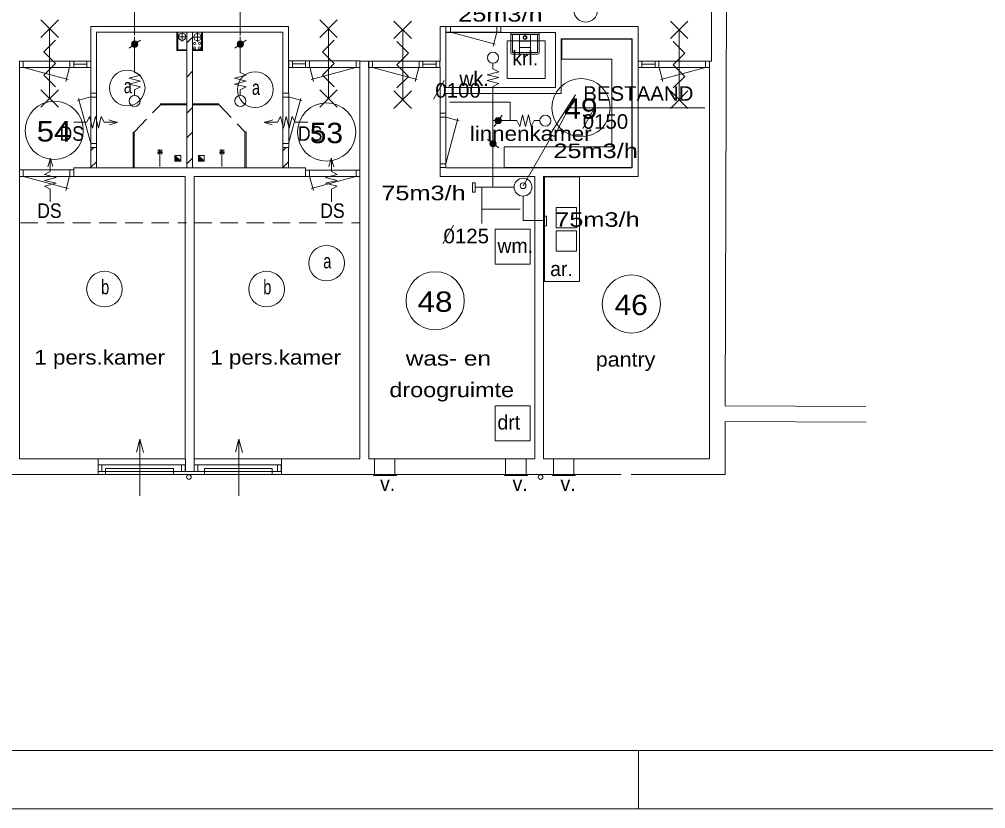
# Model space of a CAD drawing. Extents: x 295824 to 414724, y 24924 to 109024.
# Drawn here: x 320090 to 336685, y 24924 to 38482 of the extents above; entities that cross this region are included whole.
import ezdxf
from ezdxf.enums import TextEntityAlignment as Align

# ---------------------------------------------------------------- set-up
doc = ezdxf.new("R2010")
doc.units = 0
doc.header["$LTSCALE"] = 100
doc.linetypes.add('DOT_DASHED', pattern=[7.7, 5, -1.2, 0.3, -1.2])
doc.linetypes.add('MEDIUM_DASHED', pattern=[4.5, 3, -1.5])
for name, color, linetype, lineweight in [('1', 7, 'Continuous', 13), ('16', 7, 'Continuous', 13), ('24', 7, 'Continuous', 13), ('61', 7, 'Continuous', 13)]:
    doc.layers.add(name, color=color, linetype=linetype, lineweight=lineweight)

msp = doc.modelspace()

# ---------------------------------------------------------------- hatches: boundary and pattern name
at = {"layer": '24'}
for points in [[(322123.6, 38055.7, 1), (322015, 38055.7, 1)], [(323939.2, 38055.7, 1), (323830.6, 38055.7, 1)], [(328313.4, 36687.4, 1), (328313.4, 36796, 1)], [(328278.1, 36344.9, 1), (328169.5, 36344.9, 1)]]:
    msp.add_hatch(color=256, dxfattribs=at).paths.add_polyline_path(points)
at = {"layer": '61'}
for points in [[(322763.2, 36143.3), (322863.2, 36043.3), (322763.2, 36043.3)], [(323166.3, 36143.3), (323266.3, 36043.3), (323166.3, 36043.3)]]:
    msp.add_hatch(color=256, dxfattribs=at).paths.add_polyline_path(points)

# ---------------------------------------------------------------- linework, layer by layer
at = {"layer": '1'}
for p, q in [((322069.3, 38210.2), (322069.3, 39093.2)), ((323884.9, 38205.2), (323884.9, 39093.2)), ((328740.2, 35624.5), (329240.2, 36490.5)), ((330723.6, 24923.8), (330723.6, 25923.8)), ((304995.6, 24923.8), (414723.6, 24923.8))]:
    msp.add_line(p, q, dxfattribs=at)
msp.add_lwpolyline([(304995.6, 25923.8), (413723.6, 25923.8), (413723.6, 108023.8), (304995.6, 108023.8)], dxfattribs=at)
msp.add_lwpolyline([(329640.2, 37183.5), (329276.2, 36469.5), (329204.2, 36511.5)], close=True, dxfattribs=at)
msp.add_circle((328740.2, 35624.2), 50, dxfattribs=at)
at = {"layer": '16'}
for p, q in [((321396.7, 36814.4), (321346.7, 36614.4)), ((324674.2, 36814.4), (324724.2, 36614.4)), ((320520.3, 35716.2), (320720.3, 35666.2)), ((325550.6, 35716.2), (325350.6, 35666.2))]:
    msp.add_line(p, q, dxfattribs=at)
at = {"layer": '24'}
for p, q in [((322069.3, 37620.3), (322069.3, 38181)), ((323884.9, 37620.3), (323884.9, 38182.6)), ((321977.7, 37984.9), (322169.3, 38126.5)), ((323793.3, 37984.9), (323984.8, 38126.5)), ((327388, 37429.7), (327203.7, 37110.4)), ((328223.8, 37280.2), (328223.8, 35599.5)), ((329500.7, 36963.5), (331861.5, 36963.5)), ((329951, 36926.2), (329766.7, 36606.9)), ((321772.1, 36711), (321627.9, 36756)), ((321636.3, 36668.6), (321772.1, 36711)), ((324298.7, 36711), (324442.9, 36756)), ((324434.5, 36668.6), (324298.7, 36711)), ((328582.5, 36741.7), (328223.8, 36741.7)), ((328384.2, 36833.3), (328242.6, 36641.8)), ((328132.2, 36415.7), (328323.8, 36274)), ((320623.7, 36091.6), (320578.6, 35947.4)), ((320666.1, 35955.8), (320623.7, 36091.6)), ((325404.8, 35955.8), (325447.2, 36091.6)), ((325447.2, 36091.6), (325492.2, 35947.4)), ((328586.6, 35599.5), (327924, 35599.5)), ((328031, 35598.1), (328031, 34975.1)), ((328691.4, 35220.4), (328031, 35220.4)), ((327545.3, 34943.7), (327360.9, 34624.4)), ((322161, 31270.1), (322101.4, 31047.7)), ((323859.9, 31270.1), (323800.3, 31047.7))]:
    msp.add_line(p, q, dxfattribs=at)
for points in [[(328223.8, 37730.2), (328223.8, 37630.2), (328323.8, 37580.2), (328123.8, 37530.2), (328323.8, 37480.2), (328123.8, 37430.2), (328323.8, 37380.2), (328223.8, 37330.2), (328223.8, 37280.2)], [(322069.3, 37170.3), (322069.3, 37270.3), (322169.3, 37320.3), (321969.3, 37370.3), (322169.3, 37420.3), (321969.3, 37470.3), (322169.3, 37520.3), (322069.3, 37570.3), (322069.3, 37620.3)], [(323884.9, 37170.3), (323884.9, 37270.3), (323984.9, 37320.3), (323784.9, 37370.3), (323984.9, 37420.3), (323784.9, 37470.3), (323984.9, 37520.3), (323884.9, 37570.3), (323884.9, 37620.3)], [(328518.4, 36746.7), (328518.4, 37061.4), (327480.7, 37061.4)], [(329032.5, 36741.7), (328932.5, 36741.7), (328882.5, 36641.7), (328832.5, 36841.7), (328782.5, 36641.7), (328732.5, 36841.7), (328682.5, 36641.7), (328632.5, 36741.7), (328582.5, 36741.7)], [(321346.7, 36614.4), (321296.7, 36814.4), (321246.7, 36714.4), (321027.9, 36714.4)], [(321777.9, 36714.4), (321546.7, 36714.4), (321496.7, 36814.4), (321446.7, 36614.4), (321396.7, 36814.4)], [(324292.9, 36714.4), (324524.2, 36714.4), (324574.2, 36814.4), (324624.2, 36614.4), (324674.2, 36814.4)], [(324724.2, 36614.4), (324774.2, 36814.4), (324824.2, 36714.4), (325042.9, 36714.4)], [(320620.3, 36097.4), (320620.3, 35866.2), (320520.3, 35816.2), (320720.3, 35766.2), (320520.3, 35716.2)], [(325450.6, 36097.4), (325450.6, 35866.2), (325550.6, 35816.2), (325350.6, 35766.2), (325550.6, 35716.2)], [(320720.3, 35666.2), (320520.3, 35616.2), (320620.3, 35566.2), (320620.3, 35347.5)], [(325350.6, 35666.2), (325550.6, 35616.2), (325450.6, 35566.2), (325450.6, 35347.5)], [(328740.2, 35445.9), (328740.2, 35028.7), (329114.9, 35028.7)], [(322161, 30295.2), (322161, 31270.1), (322222.6, 31040)], [(323859.9, 30295.2), (323859.9, 31270.1), (323921.6, 31040)]]:
    msp.add_lwpolyline(points, dxfattribs=at)
for points in [[(327874, 35512), (327917.5, 35512), (327917.5, 35674.3), (327874, 35674.3)], [(329098.3, 34937), (329141.8, 34937), (329141.8, 35099.3), (329098.3, 35099.3)], [(321569.6, 30766), (322735.6, 30766), (322735.6, 30666), (321569.6, 30666)], [(323268.6, 30766), (324434.5, 30766), (324434.5, 30666), (323268.6, 30666)]]:
    msp.add_lwpolyline(points, close=True, dxfattribs=at)
for centre, radius in [((322069.3, 38055.7), 54.3), ((323884.9, 38055.7), 54.3), ((328223.8, 37821.9), 95), ((322069.3, 37078.6), 95), ((323884.9, 37078.6), 95), ((328313.4, 36741.7), 54.3), ((329124.2, 36741.7), 95), ((328223.8, 36344.9), 54.3), ((328740.2, 35599.5), 153.6)]:
    msp.add_circle(centre, radius, dxfattribs=at)
at = {"layer": '61'}
for p, q in [((332235.2, 39563.5), (332210.1, 31845.6)), ((320760.7, 38472.2), (320460.7, 38172.2)), ((320460.7, 38472.2), (320760.7, 38172.2)), ((325548.4, 38472.2), (325248.4, 38172.2)), ((325248.4, 38472.2), (325548.4, 38172.2)), ((326523.6, 38152.6), (326823.6, 38452.6)), ((326823.6, 38152.6), (326523.6, 38452.6)), ((327315.1, 37758.6), (327315.1, 38358.6)), ((327415.5, 38260.8), (327415.5, 38358.8)), ((327415.5, 38358.8), (328359.5, 38358.8)), ((327492.5, 38358.8), (327492.5, 38259.5)), ((328292.5, 38355.5), (328292.5, 38259.5)), ((328359.5, 38358.8), (328359.5, 38258.8)), ((331270, 38152.6), (331570, 38452.6)), ((331570, 38152.6), (331270, 38452.6)), ((320610.7, 37122.2), (320610.7, 38322.2)), ((321415.3, 37214.4), (321415.3, 38259)), ((322795.5, 38259), (322795.5, 37944)), ((322810.5, 38259), (322810.5, 37959)), ((322965.3, 35934), (322965.3, 38259)), ((323065.3, 35934), (323065.3, 38259)), ((323218.9, 38259), (323218.9, 37959)), ((323233.2, 38259), (323233.2, 37944)), ((325398.4, 37122.2), (325398.4, 38322.2)), ((326673.6, 38302.6), (326673.6, 37102.6)), ((327415.5, 38258.8), (328359.5, 38258.8)), ((327495.1, 38259.3), (328262.4, 38053.7)), ((328289.7, 38261.5), (328224.6, 38018.7)), ((328529.6, 38242.6), (328529.6, 37910.6)), ((329009.6, 38250.6), (328537.6, 38250.6)), ((328537.6, 38222.6), (329009.6, 38222.6)), ((328557.6, 37922.6), (328557.6, 38210.6)), ((328677.6, 38222.6), (328677.6, 37882.6)), ((328869.6, 38222.6), (328869.6, 37882.6)), ((328989.6, 38210.6), (328989.6, 37922.6)), ((329017.6, 37910.6), (329017.6, 38242.6)), ((331420, 38302.6), (331420, 37102.6)), ((323051.7, 38165.1), (322966.4, 38079.8)), ((324715.3, 37216.6), (324715.3, 38003.7)), ((328467.4, 37463.2), (328467.4, 38113.2)), ((328471.7, 38113), (329121.7, 38113)), ((328677.6, 38109.3), (328869.6, 38109.3)), ((329120, 37463.2), (329120, 38113.2)), ((329395.1, 38148.6), (330615.1, 38148.6)), ((330615.1, 38148.6), (330615.1, 35933.6)), ((322965.1, 37944), (322795.5, 37944)), ((322964.7, 37959), (322810.5, 37959)), ((323218.9, 37959), (323065.3, 37959)), ((323233.2, 37944), (323065.3, 37944)), ((328557.6, 37882.6), (328989.6, 37882.6)), ((328977.6, 37910.6), (328569.6, 37910.6)), ((328677.6, 37996), (328869.6, 37996)), ((320156.8, 37763.1), (320156.8, 37653.1)), ((320956.8, 37763.1), (320956.8, 37653.1)), ((321023.8, 37763.1), (321023.8, 37653.1)), ((321024.6, 37712.3), (321249.3, 37712.3)), ((321249.3, 37763.1), (321249.3, 37653.1)), ((324781.7, 37767), (324781.7, 37657)), ((325006.4, 37716.2), (324781.7, 37716.2)), ((325007.2, 37767), (325007.2, 37657)), ((325074.2, 37767), (325074.2, 37657)), ((325874.2, 37767), (325874.2, 37657)), ((325940.1, 37765.6), (325940.1, 30933.6)), ((325940.1, 37765.6), (326090.1, 37765.6)), ((326090.1, 37765.6), (326090.1, 30933.6)), ((326154.7, 37764.6), (326154.7, 37654.6)), ((326954.7, 37764.6), (326954.7, 37654.6)), ((327021.7, 37764.6), (327021.7, 37654.6)), ((327022.5, 37713.8), (327247.2, 37713.8)), ((327247.2, 37764.6), (327247.2, 37654.6)), ((330781.6, 37762.8), (330781.6, 37652.8)), ((331006.3, 37712), (330781.6, 37712)), ((331007.1, 37762.8), (331007.1, 37652.8)), ((331074.1, 37762.8), (331074.1, 37652.8)), ((331874.1, 37762.8), (331874.1, 37652.8)), ((331940.1, 37762.8), (331940.1, 30933.6)), ((331940.1, 37762.8), (331973.9, 37762.8)), ((320090.1, 37658.6), (320090.1, 30933.6)), ((320159.4, 37652.9), (320926.7, 37447.3)), ((320954, 37655.1), (320888.9, 37412.4)), ((321315.3, 37214.4), (321315.3, 37659)), ((323064.9, 37589), (322966.4, 37490.5)), ((324615.3, 37553.7), (324615.3, 37216.6)), ((325077, 37659), (325142, 37416.2)), ((325871.6, 37656.8), (325104.3, 37451.2)), ((326157.3, 37654.4), (326924.6, 37448.8)), ((326951.8, 37656.6), (326886.8, 37413.9)), ((327315.1, 36868.1), (327315.1, 37658.6)), ((331077, 37654.8), (331142, 37412.1)), ((331871.5, 37652.6), (331104.2, 37447)), ((328471.7, 37464.3), (329121.7, 37464.3)), ((320760.7, 37272.2), (320460.7, 36972.2)), ((320460.7, 37272.2), (320760.7, 36972.2)), ((321315.3, 37215.2), (321315.3, 36280.4)), ((321415.3, 37214.4), (321315.3, 37214.4)), ((321415.3, 36280.4), (321415.3, 37214.4)), ((324615.5, 36280), (324615.5, 37214)), ((324615.5, 37214), (324715.5, 37214)), ((324715.5, 37214), (324715.5, 36280)), ((325548.4, 37272.2), (325248.4, 36972.2)), ((325248.4, 37272.2), (325548.4, 36972.2)), ((326523.6, 36952.6), (326823.6, 37252.6)), ((326823.6, 36952.6), (326523.6, 37252.6)), ((331270, 36952.6), (331570, 37252.6)), ((331570, 36952.6), (331270, 37252.6)), ((321315.6, 37148.4), (321088.3, 37087.5)), ((321315.6, 36351), (321108.7, 37123.2)), ((321415.2, 37147.4), (321315.9, 37147.4)), ((322514.3, 37033.2), (322964.4, 37033.2)), ((322514.3, 37015.2), (322514.3, 37033.2)), ((322514.3, 37015.2), (322964.4, 37015.2)), ((323065.7, 37033.2), (323516, 37033.2)), ((324615.6, 37147), (324714.9, 37147)), ((324715.2, 37148), (324942.5, 37087.1)), ((324715.2, 36350.6), (324922.1, 37122.8)), ((323064.9, 36969), (322966.4, 36870.5)), ((327315.2, 35934.1), (327315.2, 36868.1)), ((327315.2, 36868.1), (327415.2, 36868.1)), ((327415.2, 36868.1), (327415.2, 35934.1)), ((321315.2, 36613.5), (321315.2, 36723.9)), ((327315.3, 36801.1), (327414.6, 36801.1)), ((327414.9, 36802.1), (327642.2, 36741.2)), ((327414.9, 36004.6), (327621.8, 36776.9)), ((322046.8, 36541.2), (322046.8, 35936.4)), ((322064.8, 36541.2), (322046.8, 36541.2)), ((322064.8, 36541.2), (322064.8, 35936.4)), ((323064.9, 36546.5), (322966.4, 36448)), ((323964.6, 36547.3), (323964.6, 35938.9)), ((323982.6, 36547.3), (323964.6, 36547.3)), ((323982.6, 36547.3), (323982.6, 35938.9)), ((321415.5, 36347.4), (321315.3, 36347.4)), ((324615.3, 36347), (324715.5, 36347)), ((321371, 36278.7), (321314.3, 36222)), ((321414.9, 36280.4), (321314.8, 36280.4)), ((321315.1, 36280.4), (321315.1, 35934)), ((321414.9, 36280), (321414.9, 35933.6)), ((322455.2, 36202.8), (322555.2, 36202.8)), ((322469.9, 36167.4), (322540.6, 36238.1)), ((322469.9, 36238.1), (322540.6, 36167.4)), ((322505.2, 36152.8), (322505.2, 36252.8)), ((323519.7, 36202.8), (323619.7, 36202.8)), ((323534.3, 36167.4), (323605, 36238.1)), ((323534.3, 36238.1), (323605, 36167.4)), ((323569.7, 36152.8), (323569.7, 36252.8)), ((324615.5, 36280), (324715.5, 36280)), ((324672.9, 36278.7), (324616.2, 36222)), ((324616.5, 36280.4), (324616.5, 35934)), ((324715.2, 36280.4), (324715.2, 35934)), ((321414.7, 36034.7), (321314.3, 35934.3)), ((322505.2, 36152.8), (322505.2, 35952.8)), ((323064.9, 36098.9), (322966.4, 36000.4)), ((323569.7, 36152.8), (323569.7, 35952.8)), ((324715.2, 36034.7), (324614.8, 35934.3)), ((320090.9, 35894.5), (320090.9, 35784.1)), ((321021.7, 35894.5), (320090.9, 35894.5)), ((320156.8, 35894.8), (320156.8, 35784.8)), ((320956.8, 35894.8), (320956.8, 35784.8)), ((321023.8, 35894.8), (321023.8, 35784.8)), ((325005, 35934), (321414.9, 35934)), ((325005.9, 35892.8), (325005.9, 35782.8)), ((325008.1, 35892.5), (325938.8, 35892.5)), ((325072.9, 35892.8), (325072.9, 35782.8)), ((325872.9, 35892.8), (325872.9, 35782.8)), ((327315, 36001.1), (327415.2, 36001.1)), ((327315.1, 35783.6), (327315.1, 35948.9)), ((327315.2, 35934.1), (327415.2, 35934.1)), ((330615.1, 35933.6), (327415.1, 35933.6)), ((322940.3, 35784), (320091, 35784)), ((320159.4, 35784.7), (320926.7, 35579.1)), ((320954, 35786.8), (320888.9, 35544.1)), ((322940.3, 35784), (320997.9, 35784)), ((323090.3, 35784), (325150.3, 35784)), ((325075.8, 35784.8), (325140.8, 35542.1)), ((325870.4, 35782.7), (325103.1, 35577.1)), ((332210.1, 31845.6), (334629.7, 31833.6)), ((321441, 30932), (321441, 30662)), ((322941, 30932), (322941, 30717.3)), ((323090, 30932), (323090, 30717.3)), ((324590, 30932), (324590, 30662)), ((328940.1, 30933.6), (326090.1, 30933.6)), ((326190.3, 30663.6), (326190.3, 30932.5)), ((326540.3, 30661.4), (326540.3, 30932.5)), ((328441.5, 30663.6), (328441.5, 30932.5)), ((328791.5, 30661.4), (328791.5, 30932.5)), ((329263.9, 30663.6), (329263.9, 30932.5)), ((329613.9, 30661.4), (329613.9, 30932.5)), ((321441.2, 30830.3), (321441.2, 30717.3)), ((323157.2, 30717.3), (321441.2, 30717.3)), ((322940.2, 30831.3), (321442.1, 30831.3)), ((321508.2, 30830.8), (321508.2, 30717.9)), ((322873.2, 30831.3), (322873.2, 30717.9)), ((322940.2, 30831.3), (322940.2, 30717.3)), ((323090.2, 30830.3), (323090.2, 30717.3)), ((324589.2, 30717.3), (323090.2, 30717.3)), ((324589.2, 30831.3), (323091.1, 30831.3)), ((323157.2, 30830.8), (323157.2, 30717.3)), ((324522.2, 30831.3), (324522.2, 30717.9)), ((324589.2, 30831.3), (324589.2, 30717.3)), ((326190, 30663.6), (307806, 30663.6)), ((326171.2, 30661.4), (326564.4, 30661.4)), ((326171.2, 30643.9), (326171.2, 30661.4)), ((326171.2, 30643.9), (326564.4, 30643.9)), ((330425.5, 30663.6), (326540.9, 30663.6)), ((326564.4, 30643.9), (326564.4, 30661.4)), ((328422.3, 30661.4), (328815.5, 30661.4)), ((328422.3, 30643.9), (328422.3, 30661.4)), ((328422.3, 30643.9), (328815.5, 30643.9)), ((328815.5, 30643.9), (328815.5, 30661.4)), ((329244.7, 30661.4), (329637.9, 30661.4)), ((329244.7, 30643.9), (329244.7, 30661.4)), ((329244.7, 30643.9), (329637.9, 30643.9)), ((329637.9, 30643.9), (329637.9, 30661.4))]:
    msp.add_line(p, q, dxfattribs=at)
at = {"layer": '61', "linetype": 'DOT_DASHED'}
for p, q in [((322801.4, 38184.2), (322965.5, 38184.2)), ((322886.5, 38258.4), (322886.5, 38099.1)), ((323061.2, 38176.8), (323225.2, 38176.8)), ((323149.7, 38257.1), (323149.7, 38093))]:
    msp.add_line(p, q, dxfattribs=at)
at = {"layer": '61', "linetype": 'MEDIUM_DASHED'}
for p, q in [((322069.1, 36548.8), (322513.1, 37016.1)), ((323523.4, 37012.1), (323965.2, 36547.1)), ((320109.5, 34984.3), (322959.5, 34984.3)), ((323093.5, 34984.3), (325940.1, 34984.3))]:
    msp.add_line(p, q, dxfattribs=at)
at = {"layer": '61'}
for points in [[(331973.9, 37762.8), (331980.4, 39563.5), (332235.2, 39563.5)], [(324715.3, 37759), (324715.3, 38359), (321315.3, 38359), (321315.3, 37759)], [(327315.1, 37758.6), (327315.1, 38358.6), (330715.1, 38358.6), (330715.1, 37758.6)], [(322940.5, 38259), (321415.3, 38259), (321415.3, 37309)], [(324615.3, 37033.2), (324615.3, 38259), (322735.3, 38259)], [(320710.7, 37322.2), (320510.7, 37522.2), (320710.7, 37722.2), (320510.7, 37922.2), (320710.7, 38122.2)], [(325498.4, 37322.2), (325298.4, 37522.2), (325498.4, 37722.2), (325298.4, 37922.2), (325498.4, 38122.2)], [(326573.6, 38102.6), (326773.6, 37902.6), (326573.6, 37702.6), (326773.6, 37502.6), (326573.6, 37302.6)], [(327415.1, 36868.1), (327415.1, 37208.6), (329395.1, 37208.6), (329395.1, 38148.6)], [(331320, 38102.6), (331520, 37902.6), (331320, 37702.6), (331520, 37502.6), (331320, 37302.6)], [(331940.1, 30933.6), (329090.1, 30933.6), (329090.1, 35783.6), (330715.1, 35783.6), (330715.1, 37658.6)], [(323065.7, 37015.2), (323516, 37015.2), (323516, 37033.2)], [(322863.2, 36043.3), (322763.2, 36043.3), (322763.2, 36143.3)], [(323266.3, 36043.3), (323166.3, 36043.3), (323166.3, 36143.3)], [(321024.3, 35784.1), (321024.3, 35934), (321429.7, 35934)], [(323090.3, 35784), (325005, 35784), (325005, 35934)], [(325938.8, 35892.5), (325938.8, 35782.1), (325005.5, 35782.1)], [(320090.1, 30933.6), (322940.1, 30933.6), (322940.1, 35783.6)], [(325940.1, 30933.6), (323090.1, 30933.6), (323090.1, 35783.6)], [(327315.1, 35783.6), (328940.1, 35783.6), (328940.1, 30933.6)], [(330595.5, 30663.6), (332210.1, 30663.6), (332210.1, 31575.6), (334631.3, 31563.6)]]:
    msp.add_lwpolyline(points, dxfattribs=at)
for points in [[(329295.1, 37308.6), (327415.1, 37308.6), (327415.1, 38258.6), (329295.1, 38258.6)], [(329404.5, 37796.7), (329404.5, 38138.6), (330607.3, 38138.6), (330607.3, 35938.9), (328417.6, 35938.9), (328417.6, 36289.2), (330262.9, 36289.2), (330262.9, 37796.7)], [(320090.9, 37762.8), (320090.9, 37652.4), (321315.2, 37652.4), (321315.2, 37762.8)], [(325940.1, 37766.6), (325940.1, 37656.3), (324715.8, 37656.3), (324715.8, 37766.6)], [(326088.8, 37764.3), (326088.8, 37653.9), (327313.1, 37653.9), (327313.1, 37764.3)], [(331940, 37762.4), (331940, 37652.1), (330715.7, 37652.1), (330715.7, 37762.4)], [(322863.2, 36043.3), (322863.2, 36143.3), (322763.2, 36143.3)], [(322763.2, 36143.3), (322863.2, 36043.3), (322763.2, 36043.3)], [(323266.3, 36043.3), (323266.3, 36143.3), (323166.3, 36143.3)], [(323166.3, 36143.3), (323266.3, 36043.3), (323166.3, 36043.3)], [(329708.5, 35776.1), (329708.5, 33976.1), (329108.5, 33976.1), (329108.5, 35776.1)], [(329657.5, 35249.9), (329657.5, 34899.9), (329307.5, 34899.9), (329307.5, 35249.9)], [(328861, 34276.5), (328261, 34276.5), (328261, 34876.5), (328861, 34876.5)], [(329657.5, 34850.5), (329657.5, 34500.5), (329307.5, 34500.5), (329307.5, 34850.5)], [(328861, 31244.8), (328261, 31244.8), (328261, 31844.8), (328861, 31844.8)]]:
    msp.add_lwpolyline(points, close=True, dxfattribs=at)
for centre, radius in [((329816.1, 38633.4), 200), ((322885.9, 38183.5), 62.5), ((323149.7, 38176.7), 62.5), ((328773.6, 38170.6), 32), ((328773.6, 38170.6), 24), ((323098, 37991.7), 20), ((323100.1, 38066.8), 20), ((323184.8, 38068.2), 20), ((323185.5, 37991.7), 20), ((321942, 37302.8), 306.3), ((324141.4, 37275), 306.3), ((329737.2, 36963), 500), ((320688.9, 36573), 500), ((325366.2, 36545.1), 500), ((325366.4, 34293.8), 306.3), ((321552.2, 33848), 306.3), ((324336.3, 33848), 306.3), ((327231.5, 33647.5), 500), ((330600.3, 33591.8), 500), ((323003.1, 30620.7), 40), ((329041.1, 30620.7), 40)]:
    msp.add_circle(centre, radius, dxfattribs=at)
for centre, radius, start, end in [((328537.6, 38242.6), 8, 90, 180), ((328537.6, 38230.6), 8, 180, 270), ((328569.6, 38210.6), 12, 90, 180), ((328977.6, 38210.6), 12, 0, 90), ((329009.6, 38242.6), 8, 0, 90), ((329009.6, 38230.6), 8, 270, 0), ((328557.6, 37910.6), 28, 180, 270), ((328569.6, 37922.6), 12, 180, 270), ((328977.6, 37922.6), 12, 270, 0), ((328989.6, 37910.6), 28, 270, 0)]:
    msp.add_arc(centre, radius, start, end, dxfattribs=at)

# ---------------------------------------------------------------- texts
at = {"layer": '24'}
for s, width, p in [('25m3/h', 1.3, (327626.5, 38442.7)), ('0100', 1.05, (327233.4, 37136.8)), ('BESTAAND', 1.05, (329773.8, 37083.3)), ('0150', 1.05, (329764.9, 36601.8)), ('DS', 0.9, (320781.5, 36395.4)), ('DS', 0.9, (324875.9, 36395.4)), ('25m3/h', 1.3, (329261.8, 36098.3)), ('75m3/h', 1.3, (326305.7, 35374.5)), ('DS', 0.9, (320398.4, 35070.4)), ('DS', 0.9, (325259, 35070.4)), ('75m3/h', 1.3, (329293.2, 34918.2)), ('0125', 1.05, (327374.9, 34635))]:
    msp.add_text(s, height=250, dxfattribs=dict(at, width=width)).set_placement(p)
at = {"layer": '61'}
for s, p in [('krl.', (328554.7, 37689.3)), ('wk.', (327647.7, 37338.5)), ('wm.', (328299.9, 34467.8)), ('ar.', (329205.8, 34071.5)), ('drt', (328299.9, 31436.1)), ('v.', (326285.6, 30382.5)), ('v.', (328560.7, 30382.5)), ('v.', (329383.1, 30382.5))]:
    msp.add_text(s, height=250, dxfattribs=at).set_placement(p)
for s, width, p in [('a', 0.75, (321884, 37213.7)), ('a', 0.75, (324083.4, 37185.8)), ('linnenkamer', 1.15, (327824.8, 36394.8)), ('a', 0.75, (325308.4, 34204.6)), ('b', 0.75, (321494.2, 33758.9)), ('b', 0.75, (324278.3, 33758.9)), ('1 pers.kamer', 1.15, (320347.6, 32552.1)), ('1 pers.kamer', 1.15, (323369.8, 32552.1)), ('was- en', 1.25, (326726.6, 32534.1)), ('pantry', 1.1, (329990.3, 32516.6)), ('droogruimte', 1.2, (326445.3, 31992.4))]:
    msp.add_text(s, height=250, dxfattribs=dict(at, width=width)).set_placement(p)
for s, width, p in [('49', 1.1, (329734.3, 36773.1)), ('54', 1.15, (320686, 36383.1)), ('53', 1.1, (325363.3, 36355.2)), ('48', 1.15, (327228.6, 33457.6)), ('46', 1.1, (330597.4, 33401.9))]:
    msp.add_text(s, height=350, dxfattribs=dict(at, width=width)).set_placement(p, align=Align.CENTER)

doc.saveas('drawing.dxf')
